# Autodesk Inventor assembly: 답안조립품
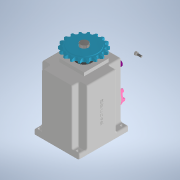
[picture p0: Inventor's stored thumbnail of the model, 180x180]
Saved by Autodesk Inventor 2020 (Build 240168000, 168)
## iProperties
Created: 2022-01
Part Number: 답안조립품
Document SubType Name: Assembly
Designer: user
Author: user
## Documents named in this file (16)
- C:\Users\user\Desktop\720112V1014\답안조립품.iam
- C:\Users\user\Desktop\720112V1014\멈춤나사 M3.ipt
- C:\Users\user\Desktop\720112V1014\메인 축.ipt
- C:\Users\user\Desktop\720112V1014\베어링 608.ipt
- C:\Users\user\Desktop\720112V1014\베어링 6003.ipt
- C:\Users\user\Desktop\720112V1014\본체.ipt
- C:\Users\user\Desktop\720112V1014\볼트 M4 x 10.ipt
- C:\Users\user\Desktop\720112V1014\부시.ipt
- C:\Users\user\Desktop\720112V1014\상부 캡.ipt
- C:\Users\user\Desktop\720112V1014\서브 축.ipt
- C:\Users\user\Desktop\720112V1014\스프로킷.ipt
- C:\Users\user\Desktop\720112V1014\슬라이더.ipt
- C:\Users\user\Desktop\720112V1014\오일 실 8 x 22 x 7.ipt
- C:\Users\user\Desktop\720112V1014\오일 실 17 x 32 x 8.ipt
- C:\Users\user\Desktop\720112V1014\커버.ipt
- C:\Users\user\Desktop\720112V1014\키 5 x 5.ipt
